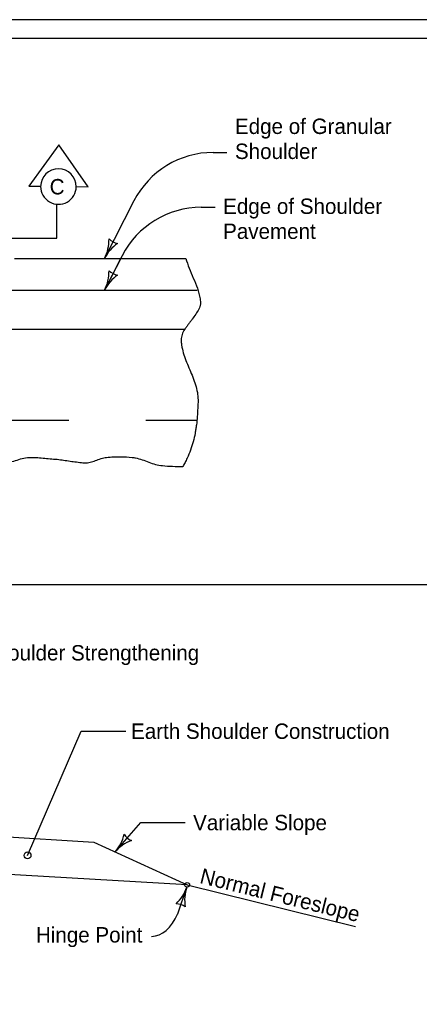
# Model space of a CAD drawing. Extents: x 8045 to 81668, y 6217 to 16762.
# Drawn here: x 11810 to 12226, y 8935 to 9944 of the extents above; entities that cross this region are included whole.
import ezdxf

# ---------------------------------------------------------------- set-up
doc = ezdxf.new("R2010")
doc.units = 0
for name, color, linetype in [('dsnStdDetailExtension', 7, 'Continuous'), ('dsnStdDimension', 7, 'Continuous'), ('dsnStdLabel', 7, 'Continuous'), ('dsnStdLineWork', 7, 'Continuous'), ('dsnStdNote', 7, 'Continuous'), ('dsnStdSection', 7, 'Continuous'), ('Level 4', 7, 'Continuous')]:
    doc.layers.add(name, color=color, linetype=linetype)

msp = doc.modelspace()

# ---------------------------------------------------------------- linework, layer by layer
at = {"layer": 'dsnStdDetailExtension'}
msp.add_circle((11818.9, 9075), 3.54, dxfattribs=at)
msp.add_circle((11818.9, 9075), 3.54, dxfattribs=at)
at = {"layer": 'dsnStdDimension'}
msp.add_line((10152.2, 9924.4), (13247.9, 9924.4), dxfattribs=at)
at = {"layer": 'dsnStdLabel'}
for p, q in [((11805.5, 9695.6), (11983.4, 9695.6)), ((11915.2, 9694.5), (11898.9, 9662.7)), ((10347.6, 9662.7), (11995.1, 9662.7)), ((10368.9, 9622), (11982.7, 9622)), ((11762.5, 9527.5), (11861.7, 9527.5)), ((11941.7, 9527.5), (11995, 9527.5)), ((11753, 9097.2), (11887.7, 9088.8)), ((11887.7, 9088.8), (11984.8, 9044.4)), ((11984.8, 9044.4), (11408.7, 9077.6)), ((11984.8, 9044.4), (12159.8, 9001))]:
    msp.add_line(p, q, dxfattribs=at)
msp.add_ellipse((11984.8, 9044.4), major_axis=(2.58, 0), ratio=0.913811, dxfattribs=at)
for points in [[(11983.4, 9695.6), (11986.8, 9685.5), (11991.2, 9675.1), (11995.4, 9664.5), (11997, 9659.1), (11998.2, 9653.6), (11998.6, 9648.2), (11998.4, 9646.9), (11998, 9645.5), (11996.9, 9642.9), (11990, 9632.4), (11988.1, 9629.8), (11986.1, 9627.2), (11984.2, 9624.5), (11982.3, 9621.9), (11979.6, 9616.5), (11978.6, 9611), (11978.8, 9607.1), (11979.4, 9603.3), (11981.4, 9595.5), (11987.5, 9579.9), (11993.5, 9564.1), (11995.4, 9556.3), (11996.1, 9548.4), (11995.8, 9539.9), (11995.3, 9531.2), (11994.5, 9522.5), (11993.8, 9518.1), (11993.1, 9513.8), (11991.1, 9505), (11988.4, 9496.4), (11984.8, 9487.8), (11982.7, 9483.5), (11981.5, 9481.3), (11980.3, 9479.2)], [(11700.5, 9482.9), (11702.5, 9483), (11710.1, 9483.5), (11717.7, 9484.2), (11725.2, 9485), (11732.8, 9485.9), (11737.5, 9486.9), (11742.2, 9488.3), (11746.9, 9489.7), (11749.2, 9490.2), (11751.6, 9490.4), (11758.1, 9490.4), (11764.7, 9489.8), (11771.3, 9488.7), (11777.8, 9487.6), (11781.8, 9486.7), (11785.8, 9485.4), (11789.8, 9484.3), (11793.8, 9483.6), (11797.3, 9483.6), (11800.9, 9484.1), (11808, 9486), (11815.1, 9488), (11822.3, 9488.7), (11836.8, 9487.8), (11851.4, 9486.5), (11858.1, 9485.6), (11864.8, 9484.6), (11871.5, 9483.7), (11878.2, 9483), (11883.9, 9483.6), (11889.6, 9485.4), (11895.3, 9487.5), (11901, 9488.7), (11908.5, 9489.2), (11916.1, 9489.4), (11927.5, 9488.7), (11931.2, 9488.2), (11938.2, 9486.3), (11945.1, 9483.8), (11952, 9481.4), (11959.1, 9480.2), (11980.3, 9479.2)]]:
    msp.add_spline(points, degree=3, dxfattribs=at)
at = {"layer": 'dsnStdLineWork'}
for p, q in [((11818.9, 9075), (11874.6, 9204.1)), ((11874.6, 9204.1), (11921, 9204.1)), ((11909.9, 9078.7), (11936.5, 9109.1)), ((11936.5, 9109.1), (11982.9, 9109.1)), ((11975, 9014.4), (11984.5, 9042))]:
    msp.add_line(p, q, dxfattribs=at)
for centre, radius, start, end in [((11877.9, 9106.6), 42.5, 318.8454, 346.9178), ((11941.9, 9050.7), 42.5, 110.7729, 138.8454), ((11933.4, 9105.5), 16.4, 211.112, 246.5787), ((11944.3, 9055.8), 42.5, 312.9788, 341.0513), ((12024.7, 9028.2), 42.5, 161.0513, 189.1238), ((11972.9, 9008.3), 16.4, 53.3179, 88.7846)]:
    msp.add_arc(centre, radius, start, end, dxfattribs=at)
msp.add_ellipse((11947.9, 9052.3), major_axis=(0, 61.5), ratio=0.559383, start_param=3.141593, end_param=4.048985, dxfattribs=at)
at = {"layer": 'dsnStdNote'}
for p, q in [((12011.8, 9805.8), (12026.1, 9805.8)), ((12011.8, 9805.8), (12026.1, 9805.8)), ((11929.5, 9755.4), (11898.9, 9695.6)), ((11929.5, 9755.4), (11898.9, 9695.6)), ((11999.5, 9748.7), (12013.8, 9748.7)), ((11999.5, 9748.7), (12013.8, 9748.7)), ((11917.2, 9698.3), (11898.9, 9662.7)), ((11917.2, 9698.3), (11898.9, 9662.7))]:
    msp.add_line(p, q, dxfattribs=at)
for centre, radius, start, end in [((12011.8, 9713.3), 92.4, 90, 152.9341), ((12011.8, 9713.3), 92.4, 90, 152.9341), ((11999.5, 9656.3), 92.4, 90, 152.9341), ((11999.5, 9656.3), 92.4, 90, 152.9341), ((11861.1, 9715), 42.5, 332.9341, 1.0066), ((11861.1, 9715), 42.5, 332.9341, 1.0066), ((11915.2, 9727.4), 16.4, 225.2008, 260.6675), ((11915.2, 9727.4), 16.4, 225.2008, 260.6675), ((11936.8, 9676.3), 42.5, 124.8616, 152.9341), ((11936.8, 9676.3), 42.5, 124.8616, 152.9341), ((11861.1, 9682), 42.5, 332.9341, 1.0066), ((11861.1, 9682), 42.5, 332.9341, 1.0066), ((11915.2, 9694.4), 16.4, 225.2008, 260.6675), ((11915.2, 9694.4), 16.4, 225.2008, 260.6675), ((11936.8, 9643.3), 42.5, 124.8616, 152.9341), ((11936.8, 9643.3), 42.5, 124.8616, 152.9341)]:
    msp.add_arc(centre, radius, start, end, dxfattribs=at)
at = {"layer": 'dsnStdSection'}
msp.add_lwpolyline([(10132.5, 9944), (13267.5, 9944), (13267.5, 7924), (10132.5, 7924)], close=True, dxfattribs=at)
at = {"layer": 'Level 4'}
for p, q in [((11849.5, 9716.5), (11849.5, 9751.9)), ((11849.5, 9716.5), (11849.5, 9751.9)), ((11761.4, 9716.5), (11849.5, 9716.5)), ((11761.4, 9716.5), (11849.5, 9716.5)), ((12307.8, 9356.4), (10152.2, 9356.4))]:
    msp.add_line(p, q, dxfattribs=at)
msp.add_lwpolyline([(11869.5, 9770.2), (11881.8, 9770.1), (11851.4, 9813.5), (11820.2, 9770.6), (11832.5, 9770.5)], dxfattribs=at)
for start, end in [(359.4792, 179.4775), (179.4775, 359.4792)]:
    msp.add_arc((11851, 9770.3), 18.5, start, end, dxfattribs=at)

# ---------------------------------------------------------------- texts
at = {"layer": 'dsnStdLineWork'}
for s, p in [('Edge of Shoulder Strengthening', (11692.8, 9277.6)), ('Earth Shoulder Construction', (11926.5, 9196.1)), ('Variable Slope', (11991, 9101.1)), ('Hinge Point', (11827.6, 8984.4))]:
    msp.add_text(s, height=16, dxfattribs=at).set_placement(p)
msp.add_text('Normal Foreslope', height=16, rotation=346.0988, dxfattribs=at).set_placement((11997, 9046.4))
at = {"layer": 'dsnStdNote'}
for s, p in [('Edge of Granular', (12034.5, 9824.9)), ('Edge of Granular', (12034.5, 9824.9)), ('Shoulder', (12034.5, 9798.9)), ('Shoulder', (12034.5, 9798.9)), ('Edge of Shoulder', (12022.2, 9741.8)), ('Edge of Shoulder', (12022.2, 9741.8)), ('Pavement', (12022.2, 9715.8)), ('Pavement', (12022.2, 9715.8))]:
    msp.add_text(s, height=16, dxfattribs=at).set_placement(p)
at = {"layer": 'Level 4'}
msp.add_text('C', height=16, dxfattribs=at).set_placement((11841.9, 9762.1))
msp.add_text('C', height=16, dxfattribs=at).set_placement((11841.9, 9762.1))

doc.saveas('drawing.dxf')
